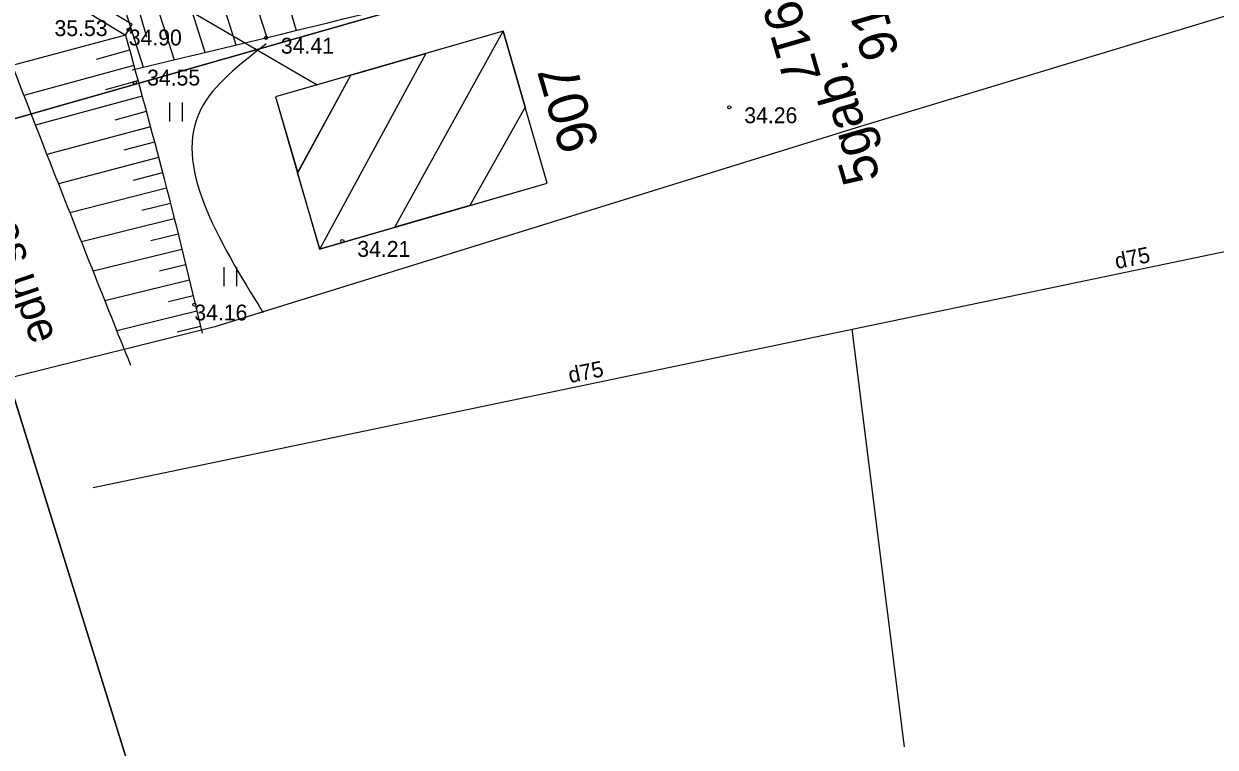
# Model space of a CAD drawing. Extents: x 469981 to 472086, y 246785 to 247785.
# Drawn here: x 471870.36 to 471907.94, y 247606.61 to 247629.44 of the extents above; entities that cross this region are included whole.
import ezdxf

# ---------------------------------------------------------------- set-up
doc = ezdxf.new("R2010")
doc.units = 0
for name, color, linetype in [('0_Ziimes', 7, 'Continuous'), ('BUVE_BDET_####_####_#', 7, 'Continuous'), ('DREN_VADP_KLKT_####_#', 7, 'Continuous'), ('DREN_VADP_KLKT_TKST_#', 7, 'Continuous'), ('HIDG_HNOS_####_TKST_#', 7, 'Continuous'), ('HIDG_PLIN_####_####_#', 7, 'Continuous'), ('RAMI_UZMR_####_####_#', 7, 'Continuous'), ('RELJ_AATZ_####_TKST_#', 7, 'Continuous'), ('RELJ_ELEM_####_####_#', 7, 'Continuous'), ('RELJ_NOGA_####_####_#', 7, 'Continuous'), ('RELJ_NOGL_####_####_#', 7, 'Continuous'), ('ROBZ_IERR_####_####_#', 7, 'Continuous'), ('ROBZ_PROJ_####_####_#', 7, 'Continuous'), ('TERT_ELEM_####_####_#', 7, 'Continuous'), ('TERT_KONT_####_####_#', 7, 'Continuous')]:
    doc.layers.add(name, color=color, linetype=linetype)

msp = doc.modelspace()

# ---------------------------------------------------------------- linework, layer by layer
at = {"layer": '0_Ziimes'}
for q in [(471874.229, 247629.034), (471879.616, 247627.516)]:
    msp.add_line((471873.663, 247630.987), q, dxfattribs=at)
for points in [[(471885.476, 247629.212), (471878.3, 247627.135), (471879.689, 247622.335), (471886.865, 247624.412), (471885.476, 247629.212)], [(471883.035, 247628.507), (471879.699, 247622.337), (471882.06, 247623.02), (471885.482, 247629.214), (471883.035, 247628.507)], [(471878.299, 247627.14), (471878.999, 247624.738), (471880.674, 247627.823), (471878.299, 247627.14)], [(471886.173, 247626.815), (471884.425, 247623.704), (471886.872, 247624.412), (471886.173, 247626.815)]]:
    msp.add_lwpolyline(points, dxfattribs=at)
for points in [[(471883.035, 247628.507), (471879.699, 247622.337), (471882.06, 247623.02), (471885.482, 247629.214)], [(471882.06, 247623.02), (471885.482, 247629.214), (471886.171, 247626.812), (471884.425, 247623.704)], [(471879.699, 247622.337), (471878.994, 247624.735), (471880.674, 247627.823), (471883.035, 247628.507)], [(471878.299, 247627.14), (471878.999, 247624.738), (471880.674, 247627.823)], [(471886.173, 247626.815), (471884.425, 247623.704), (471886.872, 247624.412)]]:
    msp.add_lwpolyline(points, close=True, dxfattribs=at)
at = {"layer": 'BUVE_BDET_####_####_#'}
for p, q in [((471871.947, 247630.539), (471873.773, 247629.431)), ((471871.856, 247630.126), (471873.565, 247629.089)), ((471873.565, 247629.089), (471873.773, 247629.431))]:
    msp.add_line(p, q, dxfattribs=at)
at = {"layer": 'DREN_VADP_KLKT_####_#'}
for points in [[(471872.545, 247614.805), (471946.806, 247630.31)], [(471896.476, 247619.803), (471898.129, 247606.619)]]:
    msp.add_lwpolyline(points, dxfattribs=at)
at = {"layer": 'HIDG_PLIN_####_####_#'}
msp.add_spline([(471869.552, 247629.259), (471871.287, 247624.807), (471873.722, 247618.674)], degree=3, dxfattribs=at)
at = {"layer": 'RAMI_UZMR_####_####_#'}
msp.add_lwpolyline([(471992.625, 247639.911), (471978.929, 247639.033), (471971.379, 247638.506), (471964.355, 247639.736), (471949.429, 247641.142), (471936.787, 247638.33), (471896.752, 247626.205), (471876.383, 247619.88), (471870.062, 247618.298), (471864.969, 247617.068), (471858.999, 247613.729), (471848.639, 247612.324), (471820.308, 247604.26)], dxfattribs=at)
at = {"layer": 'RELJ_ELEM_####_####_#'}
for centre in [(471873.669, 247629.26), (471877.996, 247629.001), (471873.86, 247627.582), (471892.612, 247626.806), (471880.405, 247622.588), (471875.738, 247620.58)]:
    msp.add_circle(centre, 0.05, dxfattribs=at)
at = {"layer": 'RELJ_NOGA_####_####_#'}
for p, q in [((471878.091, 247632.105), (471878.955, 247629.23)), ((471877.136, 247631.811), (471878.02, 247629.007)), ((471875.229, 247631.207), (471876.073, 247628.543)), ((471876.182, 247631.509), (471877.049, 247628.775)), ((471874.276, 247630.905), (471875.098, 247628.31)), ((471873.323, 247630.603), (471874.123, 247628.078)), ((471873.565, 247629.089), (471869.994, 247628.124)), ((471873.696, 247628.606), (471872.64, 247628.321)), ((471873.827, 247628.124), (471870.361, 247627.181)), ((471873.958, 247627.641), (471872.934, 247627.363)), ((471874.089, 247627.159), (471870.725, 247626.243)), ((471874.221, 247626.676), (471873.227, 247626.406)), ((471874.351, 247626.194), (471871.089, 247625.313)), ((471874.481, 247625.711), (471873.518, 247625.453)), ((471874.609, 247625.228), (471871.449, 247624.395)), ((471874.736, 247624.744), (471873.804, 247624.502)), ((471874.861, 247624.26), (471871.812, 247623.477)), ((471874.983, 247623.775), (471874.086, 247623.549)), ((471875.105, 247623.29), (471872.176, 247622.559)), ((471875.225, 247622.805), (471874.365, 247622.592)), ((471875.344, 247622.319), (471872.544, 247621.636)), ((471875.463, 247621.833), (471874.643, 247621.633)), ((471875.581, 247621.348), (471872.916, 247620.699)), ((471875.699, 247620.862), (471874.92, 247620.672)), ((471875.818, 247620.376), (471873.291, 247619.758)), ((471875.937, 247619.89), (471875.199, 247619.709))]:
    msp.add_line(p, q, dxfattribs=at)
msp.add_spline([(471873.565, 247629.089), (471874.785, 247624.555), (471875.988, 247619.682)], degree=3, dxfattribs=at)
at = {"layer": 'RELJ_NOGL_####_####_#'}
msp.add_spline([(471873.775, 247627.995), (471877.996, 247629.001), (471893.546, 247633.06), (471916.609, 247640.032), (471940.388, 247647.116), (471963.51, 247654.569), (471969.26, 247654.727), (471970.873, 247652.327), (471971.171, 247640.235), (471971.159, 247637.819)], degree=3, dxfattribs=at)
at = {"layer": 'ROBZ_IERR_####_####_#'}
for points in [[(471879.163, 247574.024), (471880.66, 247583.5), (471867.531, 247625.725), (471968.24, 247654.462), (471970.607, 247591.56)], [(471698.774, 247491.509), (471700.012, 247564.123), (471757.886, 247600.963), (471769.199, 247605.751), (471808.63, 247612.294), (471827.071, 247615.935), (471867.531, 247625.725), (471880.66, 247583.5), (471879.601, 247576.793)]]:
    msp.add_lwpolyline(points, dxfattribs=at)
at = {"layer": 'ROBZ_PROJ_####_####_#'}
msp.add_lwpolyline([(471863.461, 247637.05), (471968.166, 247666.92), (471968.24, 247654.462), (471867.531, 247625.725)], close=True, dxfattribs=at)
msp.add_lwpolyline([(471863.461, 247637.05), (471968.166, 247666.92), (471968.24, 247654.462), (471867.531, 247625.725)], close=True, dxfattribs=at)
at = {"layer": 'TERT_ELEM_####_####_#'}
for p, q in [((471874.965, 247626.359), (471874.965, 247626.959)), ((471875.365, 247626.359), (471875.365, 247626.959)), ((471876.679, 247621.165), (471876.679, 247621.765)), ((471877.079, 247621.165), (471877.079, 247621.765))]:
    msp.add_line(p, q, dxfattribs=at)
at = {"layer": 'TERT_KONT_####_####_#'}
msp.add_spline([(471878.001, 247628.809), (471875.944, 247626.751), (471877.903, 247620.332)], degree=3, dxfattribs=at)

# ---------------------------------------------------------------- texts
at = {"layer": '0_Ziimes'}
for s, height, rotation, p in [('918', 1.1813, 106.1489, (471897.986, 247628.5)), ('917', 1.1813, 286.1489, (471893.648, 247629.955)), ('5gab.', 1.1813, 106.1489, (471897.383, 247624.574)), ('907', 1.25, 106.1407, (471888.519, 247625.612))]:
    msp.add_text(s, height=height, rotation=rotation, dxfattribs=at).set_placement(p)
at = {"layer": 'DREN_VADP_KLKT_TKST_#'}
for p in [(471904.829, 247621.699), (471887.589, 247618.099)]:
    msp.add_text('d75', height=0.5, rotation=11.7936, dxfattribs=at).set_placement(p)
at = {"layer": 'HIDG_HNOS_####_TKST_#'}
msp.add_text('Ķives upe', height=1, rotation=288.7689, dxfattribs=at).set_placement((471868.73, 247624.844))
at = {"layer": 'RELJ_AATZ_####_TKST_#'}
for s, p in [('35.53', (471871.327, 247629.055)), ('34.90', (471873.669, 247628.76)), ('34.41', (471878.469, 247628.501)), ('34.55', (471874.248, 247627.495)), ('34.26', (471893.086, 247626.306)), ('34.21', (471880.878, 247622.088)), ('34.16', (471875.738, 247620.08))]:
    msp.add_text(s, height=0.5, dxfattribs=at).set_placement(p)

doc.saveas('drawing.dxf')
